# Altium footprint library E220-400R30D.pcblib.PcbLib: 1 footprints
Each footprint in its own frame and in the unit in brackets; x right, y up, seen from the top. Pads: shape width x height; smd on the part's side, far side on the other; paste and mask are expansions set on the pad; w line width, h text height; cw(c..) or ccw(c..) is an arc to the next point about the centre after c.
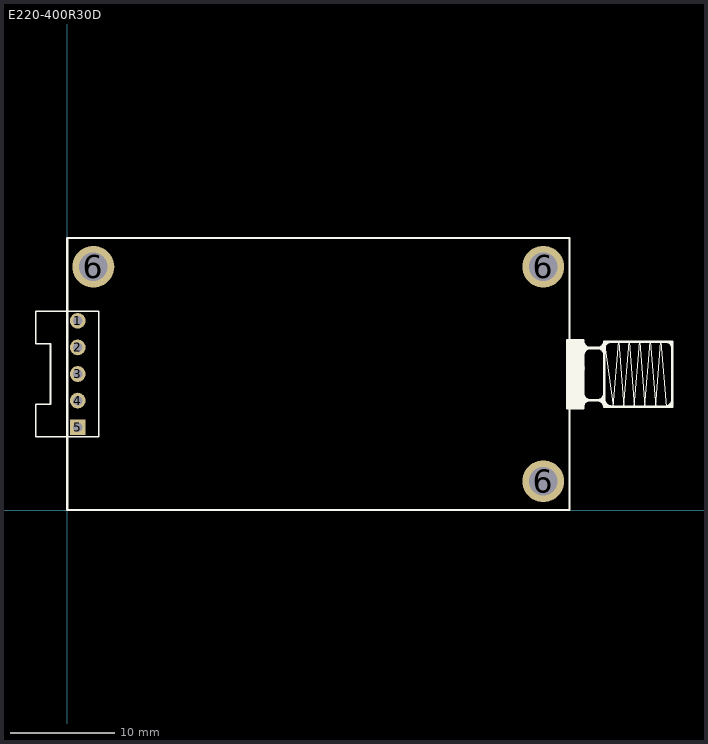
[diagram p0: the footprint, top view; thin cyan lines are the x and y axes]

## E220-400R30D [mm]
pads (8):
  round 1.5 hole 0.9: 1(1,18.08) 2(1,15.54) 3(1,13) 4(1,10.46)
  rect 1.5x1.5 hole 0.9: 5(1,7.92)
  round 4 hole 2.7: 6(2.5,23.25) 6(45.5,2.75) 6(45.5,23.25)
Top Overlay:
  rectangle: 47.821,9.74 49.321,16.24
  rectangle: 47.821,9.735 49.321,16.235
  lines w0.1: 52.171,9.885 51.321,16.085 52.171,9.885 ; 52.171,9.885 52.691,16.085 ; 52.171,9.885 52.691,16.085 ; 52.691,16.085 53.201,9.885 ; 52.691,16.085 53.201,9.885 ; 53.201,9.885 53.711,16.085 ; 53.201,9.885 53.711,16.085 ; 53.711,16.085 54.191,9.885 ; 53.711,16.085 54.191,9.885 ; 54.191,9.885 54.711,16.085 ; 54.191,9.885 54.711,16.085 ; 54.711,16.085 55.221,9.885 ; 54.711,16.085 55.221,9.885 ; 55.221,9.885 55.711,16.085 ; 55.221,9.885 55.711,16.085 ; 55.711,16.085 56.231,9.885 ; 55.711,16.085 56.231,9.885 ; 56.231,9.885 56.751,16.085 ; 56.231,9.885 56.751,16.085 ; 56.751,16.085 57.261,9.885 56.751,16.085
  lines w0.15: -3,7 -3,10.1 -1.6,10.1 -1.6,15.9 -3,15.9 -3,19 3,19 3,7 -3,7
  lines w0.2: 0,0 0,26 48,26 48,0 0,0
  lines w0.254: 47.821,9.735 47.821,16.235 ; 47.821,9.735 49.321,9.735 ; 47.821,9.735 47.821,16.235 ; 47.821,9.735 49.321,9.735 ; 47.821,16.235 49.321,16.235 ; 47.821,16.235 49.321,16.235 ; 49.321,9.735 49.321,16.235 ; 49.321,9.735 49.321,16.235 ; 49.321,11.135 ccw(c49.971,11.135) 49.971,10.485 ; 49.321,11.135 ccw(c49.971,11.135) 49.971,10.485 ; 49.321,11.135 49.321,11.505 49.321,11.135 ; 49.321,14.785 cw(c50.021,14.785) 50.021,15.485 ; 49.321,14.785 cw(c50.021,14.785) 50.021,15.485 ; 49.321,14.785 49.321,13.865 49.321,14.785 ; 49.321,16.115 ccw(c49.951,16.115) 49.951,15.485 ; 49.321,16.115 ccw(c49.951,16.115) 49.951,15.485 ; 49.321,16.115 49.321,16.235 ; 49.321,16.115 49.321,16.235 ; 49.871,10.485 ccw(c49.871,9.935) 49.321,9.935 cw(c49.871,9.935) 49.871,10.485 ; 49.871,10.485 50.721,10.485 ; 49.871,10.485 50.721,10.485 ; 49.951,15.485 50.721,15.485 ; 49.951,15.485 50.721,15.485 ; 49.971,10.485 50.691,10.485 ; 49.971,10.485 50.691,10.485 ; 50.021,15.485 50.721,15.485 ; 50.021,15.485 50.721,15.485 ; 50.691,10.485 ccw(c50.691,11.115) 51.321,11.115 cw(c50.691,11.115) 50.691,10.485 ; 50.721,10.485 cw(c50.721,9.885) 51.321,9.885 ; 50.721,10.485 cw(c50.721,9.885) 51.321,9.885 ; 50.721,15.485 ccw(c50.721,16.085) 51.321,16.085 ; 50.721,15.485 cw(c50.721,14.885) 51.321,14.885 ccw(c50.721,14.885) 50.721,15.485 ; 50.721,15.485 ccw(c50.721,16.085) 51.321,16.085 ; 51.321,9.885 57.821,9.885 ; 51.321,9.885 51.321,16.085 ; 51.321,9.885 57.821,9.885 ; 51.321,9.885 51.321,16.085 ; 51.321,16.085 57.821,16.085 ; 51.321,16.085 57.821,16.085 ; 52.001,9.885 cw(c52.001,10.565) 51.321,10.565 ccw(c52.001,10.565) 52.001,9.885 ; 52.001,9.885 52.151,9.885 52.001,9.885 ; 57.201,9.885 ccw(c57.201,10.505) 57.821,10.505 cw(c57.201,10.505) 57.201,9.885 ; 57.201,9.885 56.971,9.885 57.201,9.885 ; 57.281,16.085 cw(c57.281,15.545) 57.821,15.545 ccw(c57.281,15.545) 57.281,16.085 ; 57.281,16.085 56.881,16.085 57.281,16.085 ; 57.821,9.885 57.821,16.085 ; 57.821,9.885 57.821,16.085 ; 49.151,10.485 51.321,10.485 49.151,10.485 ; 49.321,15.485 51.321,15.485 49.321,15.485 ; 51.321,15.475 cw(c51.931,15.475) 51.931,16.085 ccw(c51.931,15.475) 51.321,15.475
  text "9" at 48.6,12.522 h2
